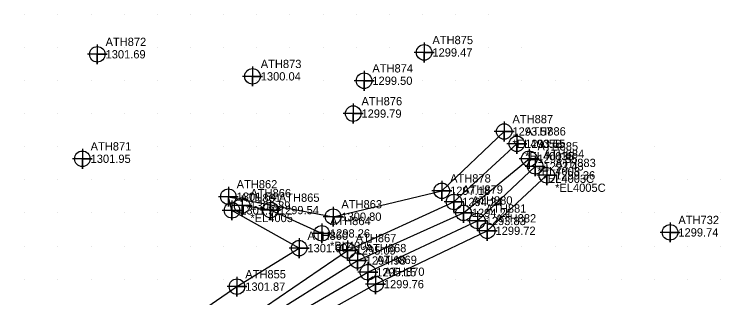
# Model space of a CAD drawing. Extents: x 1234484 to 1235382, y 695050 to 695510.
# Drawn here: x 1234936.8 to 1235150, y 695354.3 to 695440 of the extents above; entities that cross this region are included whole.
import ezdxf

# ---------------------------------------------------------------- set-up
doc = ezdxf.new("R2010")
doc.units = 0
for name, color, linetype in [('Exist DTM Breakline', 7, 'Continuous'), ('Exist DTM Breakline Cogo Comment', 7, 'Continuous'), ('Exist DTM Breakline Cogo Elevation', 7, 'Continuous'), ('Exist DTM Breakline Cogo Number', 7, 'Continuous'), ('Exist DTM Breakline Cogo Point CELL', 7, 'Continuous'), ('Exist DTM Breakline Underwater', 7, 'Continuous'), ('Exist DTM Drainline Cogo Comment', 7, 'Continuous'), ('Exist DTM Drainline Cogo Elevation', 7, 'Continuous'), ('Exist DTM Drainline Cogo Number', 7, 'Continuous'), ('Exist DTM Drainline Cogo Point CELL', 7, 'Continuous'), ('Exist DTM QL2 LIDAR Elevation Point', 7, 'Continuous'), ('Exist DTM Regular Point CELL', 7, 'Continuous'), ('Exist DTM Regular Point Cogo Elevation', 7, 'Continuous'), ('Exist DTM Regular Point Cogo Number', 7, 'Continuous'), ('Exist DTM Regular Point Underwater CELL', 7, 'Continuous'), ('Exist DTM Regular Point Underwater Cogo Comment', 7, 'Continuous'), ('Exist DTM Regular Point Underwater Cogo Elevation', 7, 'Continuous'), ('Exist DTM Regular Point Underwater Cogo Number', 7, 'Continuous'), ('Exist Hydro Stream or Body of Water', 7, 'Continuous')]:
    doc.layers.add(name, color=color, linetype=linetype)

msp = doc.modelspace()

# ---------------------------------------------------------------- linework, layer by layer
at = {"layer": 'Exist DTM Breakline'}
for points in [[(1234947.461, 695330.8), (1234981.356, 695342.155), (1235004.028, 695357.73), (1235022.786, 695369.361), (1235002.521, 695380.756), (1235001.421, 695384.893), (1235033.023, 695378.856), (1235065.819, 695386.67), (1235084.63, 695404.567)], [(1234978.66, 695327.276), (1234992.748, 695333.364), (1235012.047, 695339.528), (1235045.835, 695358.491), (1235079.523, 695374.606), (1235097.5, 695391.337)], [(1235029.585, 695373.809), (1235014.159, 695380.841), (1235005.572, 695382.217)]]:
    msp.add_lwpolyline(points, dxfattribs=at)
at = {"layer": 'Exist DTM Breakline Cogo Point CELL'}
for points in [[(1235084.63, 695407.567), (1235084.63, 695401.567), (1235084.63, 695404.567), (1235087.63, 695404.567), (1235081.63, 695404.567)], [(1235097.5, 695394.337), (1235097.5, 695388.337), (1235097.5, 695391.337), (1235100.5, 695391.337), (1235094.5, 695391.337)], [(1235065.819, 695389.67), (1235065.819, 695383.67), (1235065.819, 695386.67), (1235068.819, 695386.67), (1235062.819, 695386.67)], [(1235001.421, 695387.893), (1235001.421, 695381.893), (1235001.421, 695384.893), (1235004.421, 695384.893), (1234998.421, 695384.893)], [(1235005.572, 695385.217), (1235005.572, 695379.217), (1235005.572, 695382.217), (1235008.572, 695382.217), (1235002.572, 695382.217)], [(1235002.521, 695383.756), (1235002.521, 695377.756), (1235002.521, 695380.756), (1235005.521, 695380.756), (1234999.521, 695380.756)], [(1235014.159, 695383.841), (1235014.159, 695377.841), (1235014.159, 695380.841), (1235017.159, 695380.841), (1235011.159, 695380.841)], [(1235033.023, 695381.856), (1235033.023, 695375.856), (1235033.023, 695378.856), (1235036.023, 695378.856), (1235030.023, 695378.856)], [(1235079.523, 695377.606), (1235079.523, 695371.606), (1235079.523, 695374.606), (1235082.523, 695374.606), (1235076.523, 695374.606)], [(1235029.585, 695376.809), (1235029.585, 695370.809), (1235029.585, 695373.809), (1235032.585, 695373.809), (1235026.585, 695373.809)], [(1235022.786, 695372.361), (1235022.786, 695366.361), (1235022.786, 695369.361), (1235025.786, 695369.361), (1235019.786, 695369.361)], [(1235004.028, 695360.73), (1235004.028, 695354.73), (1235004.028, 695357.73), (1235007.028, 695357.73), (1235001.028, 695357.73)], [(1235045.835, 695361.491), (1235045.835, 695355.491), (1235045.835, 695358.491), (1235048.835, 695358.491), (1235042.835, 695358.491)]]:
    msp.add_lwpolyline(points, dxfattribs=at)
for centre in [(1235084.63, 695404.567), (1235097.5, 695391.337), (1235065.819, 695386.67), (1235001.421, 695384.893), (1235005.572, 695382.217), (1235002.521, 695380.756), (1235014.159, 695380.841), (1235033.023, 695378.856), (1235029.585, 695373.809), (1235079.523, 695374.606), (1235022.786, 695369.361), (1235045.835, 695358.491), (1235004.028, 695357.73)]:
    msp.add_circle(centre, 2.344, dxfattribs=at)
at = {"layer": 'Exist DTM Breakline Underwater'}
msp.add_lwpolyline([(1234766.421, 695209.389), (1234812.885, 695247.237), (1234843.411, 695272.621), (1234869.986, 695279.055), (1234895.378, 695289.036), (1234916.238, 695295.408), (1234934.131, 695306.081), (1234961.466, 695329.617), (1234991.436, 695342.664), (1235009.265, 695346.147), (1235040.352, 695365.623), (1235072.367, 695380.008), (1235092.174, 695396.335)], dxfattribs=at)
at = {"layer": 'Exist DTM Drainline Cogo Point CELL'}
for points in [[(1235088.448, 695403.861), (1235088.448, 695397.861), (1235088.448, 695400.861), (1235091.448, 695400.861), (1235085.448, 695400.861)], [(1235094.01, 695397.044), (1235094.01, 695391.044), (1235094.01, 695394.044), (1235097.01, 695394.044), (1235091.01, 695394.044)], [(1235069.491, 695386.302), (1235069.491, 695380.302), (1235069.491, 695383.302), (1235072.491, 695383.302), (1235066.491, 695383.302)], [(1235076.562, 695380.561), (1235076.562, 695374.561), (1235076.562, 695377.561), (1235079.562, 695377.561), (1235073.562, 695377.561)], [(1235037.336, 695371.653), (1235037.336, 695365.653), (1235037.336, 695368.653), (1235040.336, 695368.653), (1235034.336, 695368.653)], [(1235043.523, 695365.073), (1235043.523, 695359.073), (1235043.523, 695362.073), (1235046.523, 695362.073), (1235040.523, 695362.073)]]:
    msp.add_lwpolyline(points, dxfattribs=at)
for centre in [(1235088.448, 695400.861), (1235094.01, 695394.044), (1235069.491, 695383.302), (1235076.562, 695377.561), (1235037.336, 695368.653), (1235043.523, 695362.073)]:
    msp.add_circle(centre, 2.344, dxfattribs=at)
at = {"layer": 'Exist DTM QL2 LIDAR Elevation Point'}
for p, q in [((1234940, 695440), (1234940, 695440)), ((1234950, 695440), (1234950, 695440)), ((1234960, 695440), (1234960, 695440)), ((1234970, 695440), (1234970, 695440)), ((1234980, 695440), (1234980, 695440)), ((1234990, 695440), (1234990, 695440)), ((1235000, 695440), (1235000, 695440)), ((1235010, 695440), (1235010, 695440)), ((1235020, 695440), (1235020, 695440)), ((1235030, 695440), (1235030, 695440)), ((1235040, 695440), (1235040, 695440)), ((1235050, 695440), (1235050, 695440)), ((1235060, 695440), (1235060, 695440)), ((1235070, 695440), (1235070, 695440)), ((1235080, 695440), (1235080, 695440)), ((1234940, 695430), (1234940, 695430)), ((1234950, 695430), (1234950, 695430)), ((1234960, 695430), (1234960, 695430)), ((1234970, 695430), (1234970, 695430)), ((1234980, 695430), (1234980, 695430)), ((1234990, 695430), (1234990, 695430)), ((1235000, 695430), (1235000, 695430)), ((1235010, 695430), (1235010, 695430)), ((1235020, 695430), (1235020, 695430)), ((1235030, 695430), (1235030, 695430)), ((1235040, 695430), (1235040, 695430)), ((1235050, 695430), (1235050, 695430)), ((1235060, 695430), (1235060, 695430)), ((1235070, 695430), (1235070, 695430)), ((1235080, 695430), (1235080, 695430)), ((1235090, 695430), (1235090, 695430)), ((1234940, 695420), (1234940, 695420)), ((1234950, 695420), (1234950, 695420)), ((1234960, 695420), (1234960, 695420)), ((1234970, 695420), (1234970, 695420)), ((1234980, 695420), (1234980, 695420)), ((1234990, 695420), (1234990, 695420)), ((1235000, 695420), (1235000, 695420)), ((1235010, 695420), (1235010, 695420)), ((1235020, 695420), (1235020, 695420)), ((1235030, 695420), (1235030, 695420)), ((1235040, 695420), (1235040, 695420)), ((1235050, 695420), (1235050, 695420)), ((1235060, 695420), (1235060, 695420)), ((1235070, 695420), (1235070, 695420)), ((1235080, 695420), (1235080, 695420)), ((1235090, 695420), (1235090, 695420)), ((1235100, 695420), (1235100, 695420)), ((1235110, 695420), (1235110, 695420)), ((1234940, 695410), (1234940, 695410)), ((1234950, 695410), (1234950, 695410)), ((1234960, 695410), (1234960, 695410)), ((1234970, 695410), (1234970, 695410)), ((1234980, 695410), (1234980, 695410)), ((1234990, 695410), (1234990, 695410)), ((1235000, 695410), (1235000, 695410)), ((1235010, 695410), (1235010, 695410)), ((1235020, 695410), (1235020, 695410)), ((1235030, 695410), (1235030, 695410)), ((1235040, 695410), (1235040, 695410)), ((1235050, 695410), (1235050, 695410)), ((1235060, 695410), (1235060, 695410)), ((1235070, 695410), (1235070, 695410)), ((1235080, 695410), (1235080, 695410)), ((1234940, 695400), (1234940, 695400)), ((1234950, 695400), (1234950, 695400)), ((1234960, 695400), (1234960, 695400)), ((1234970, 695400), (1234970, 695400)), ((1234980, 695400), (1234980, 695400)), ((1234990, 695400), (1234990, 695400)), ((1235000, 695400), (1235000, 695400)), ((1235010, 695400), (1235010, 695400)), ((1235020, 695400), (1235020, 695400)), ((1235030, 695400), (1235030, 695400)), ((1235040, 695400), (1235040, 695400)), ((1235050, 695400), (1235050, 695400)), ((1235060, 695400), (1235060, 695400)), ((1235070, 695400), (1235070, 695400)), ((1235130, 695400), (1235130, 695400)), ((1234940, 695390), (1234940, 695390)), ((1234950, 695390), (1234950, 695390)), ((1234960, 695390), (1234960, 695390)), ((1234970, 695390), (1234970, 695390)), ((1234980, 695390), (1234980, 695390)), ((1234990, 695390), (1234990, 695390)), ((1235000, 695390), (1235000, 695390)), ((1235030, 695390), (1235030, 695390)), ((1235040, 695390), (1235040, 695390)), ((1235050, 695390), (1235050, 695390)), ((1235120, 695390), (1235120, 695390)), ((1235130, 695390), (1235130, 695390)), ((1235140, 695390), (1235140, 695390)), ((1235150, 695390), (1235150, 695390)), ((1234940, 695380), (1234940, 695380)), ((1234950, 695380), (1234950, 695380)), ((1234960, 695380), (1234960, 695380)), ((1234970, 695380), (1234970, 695380)), ((1234980, 695380), (1234980, 695380)), ((1234990, 695380), (1234990, 695380)), ((1235110, 695380), (1235110, 695380)), ((1235120, 695380), (1235120, 695380)), ((1235130, 695380), (1235130, 695380)), ((1235140, 695380), (1235140, 695380)), ((1235150, 695380), (1235150, 695380)), ((1234940, 695370), (1234940, 695370)), ((1234950, 695370), (1234950, 695370)), ((1234960, 695370), (1234960, 695370)), ((1234970, 695370), (1234970, 695370)), ((1234980, 695370), (1234980, 695370)), ((1234990, 695370), (1234990, 695370)), ((1235000, 695370), (1235000, 695370)), ((1235010, 695370), (1235010, 695370)), ((1235090, 695370), (1235090, 695370)), ((1235100, 695370), (1235100, 695370)), ((1235110, 695370), (1235110, 695370)), ((1235120, 695370), (1235120, 695370)), ((1235130, 695370), (1235130, 695370)), ((1235140, 695370), (1235140, 695370)), ((1235150, 695370), (1235150, 695370)), ((1234940, 695360), (1234940, 695360)), ((1234950, 695360), (1234950, 695360)), ((1234960, 695360), (1234960, 695360)), ((1234970, 695360), (1234970, 695360)), ((1234980, 695360), (1234980, 695360)), ((1234990, 695360), (1234990, 695360)), ((1235000, 695360), (1235000, 695360)), ((1235060, 695360), (1235060, 695360)), ((1235070, 695360), (1235070, 695360)), ((1235080, 695360), (1235080, 695360)), ((1235090, 695360), (1235090, 695360)), ((1235100, 695360), (1235100, 695360)), ((1235110, 695360), (1235110, 695360)), ((1235120, 695360), (1235120, 695360)), ((1235130, 695360), (1235130, 695360)), ((1235140, 695360), (1235140, 695360)), ((1235150, 695360), (1235150, 695360))]:
    msp.add_line(p, q, dxfattribs=at)
at = {"layer": 'Exist DTM Regular Point CELL'}
for points in [[(1234961.883, 695430.879), (1234961.883, 695424.879), (1234961.883, 695427.879), (1234964.883, 695427.879), (1234958.883, 695427.879)], [(1235060.481, 695431.438), (1235060.481, 695425.438), (1235060.481, 695428.438), (1235063.481, 695428.438), (1235057.481, 695428.438)], [(1235008.7, 695424.215), (1235008.7, 695418.215), (1235008.7, 695421.215), (1235011.7, 695421.215), (1235005.7, 695421.215)], [(1235042.367, 695422.889), (1235042.367, 695416.889), (1235042.367, 695419.889), (1235045.367, 695419.889), (1235039.367, 695419.889)], [(1235039.088, 695412.974), (1235039.088, 695406.974), (1235039.088, 695409.974), (1235042.088, 695409.974), (1235036.088, 695409.974)], [(1234957.375, 695399.332), (1234957.375, 695393.332), (1234957.375, 695396.332), (1234960.375, 695396.332), (1234954.375, 695396.332)], [(1235134.683, 695377.109), (1235134.683, 695371.109), (1235134.683, 695374.109), (1235137.683, 695374.109), (1235131.683, 695374.109)]]:
    msp.add_lwpolyline(points, dxfattribs=at)
for centre in [(1235060.481, 695428.438), (1234961.883, 695427.879), (1235008.7, 695421.215), (1235042.367, 695419.889), (1235039.088, 695409.974), (1234957.375, 695396.332), (1235134.683, 695374.109)]:
    msp.add_circle(centre, 2.344, dxfattribs=at)
at = {"layer": 'Exist DTM Regular Point Underwater CELL'}
for points in [[(1235092.174, 695399.335), (1235092.174, 695393.335), (1235092.174, 695396.335), (1235095.174, 695396.335), (1235089.174, 695396.335)], [(1235072.367, 695383.008), (1235072.367, 695377.008), (1235072.367, 695380.008), (1235075.367, 695380.008), (1235069.367, 695380.008)], [(1235040.352, 695368.623), (1235040.352, 695362.623), (1235040.352, 695365.623), (1235043.352, 695365.623), (1235037.352, 695365.623)]]:
    msp.add_lwpolyline(points, dxfattribs=at)
for centre in [(1235092.174, 695396.335), (1235072.367, 695380.008), (1235040.352, 695365.623)]:
    msp.add_circle(centre, 2.344, dxfattribs=at)
at = {"layer": 'Exist Hydro Stream or Body of Water'}
for points in [[(1234766.439, 695214.543), (1234809.451, 695250.146), (1234840.783, 695273.683), (1234870.231, 695281.467), (1234894.384, 695292.767), (1234915.014, 695298.345), (1234929.933, 695306.511), (1234953.845, 695329.807), (1234986.204, 695341.472), (1235008.526, 695348.915), (1235037.336, 695368.653), (1235069.491, 695383.302), (1235088.448, 695400.861)], [(1234938.044, 695305.366), (1234971.304, 695328.94), (1234992.169, 695338.626), (1235010.649, 695342.979), (1235043.523, 695362.073), (1235076.562, 695377.561), (1235094.01, 695394.044)]]:
    msp.add_lwpolyline(points, dxfattribs=at)

# ---------------------------------------------------------------- texts
at = {"layer": 'Exist DTM Breakline Cogo Comment'}
for s, p in [('*EL4005B', (1235087.13, 695399.567)), ('*EL4005C', (1235100, 695386.337)), ('*EL4005', (1235008.072, 695377.217)), ('*BL4005', (1235032.085, 695368.809))]:
    msp.add_text(s, height=2.5, dxfattribs=at).set_placement(p)
at = {"layer": 'Exist DTM Breakline Cogo Elevation'}
for s, p in [('1293.57', (1235087.13, 695403.317)), ('1299.36', (1235100, 695390.087)), ('1301.64', (1235003.921, 695383.643)), ('1297.18', (1235068.319, 695385.42)), ('1301.91', (1235005.021, 695379.506)), ('1300.89', (1235008.072, 695380.967)), ('1299.54', (1235016.659, 695379.591)), ('1300.80', (1235035.523, 695377.606)), ('1299.72', (1235082.023, 695373.356)), ('1298.26', (1235032.085, 695372.559)), ('1301.60', (1235025.286, 695368.111)), ('1301.87', (1235006.528, 695356.48)), ('1299.76', (1235048.335, 695357.241))]:
    msp.add_text(s, height=2.5, dxfattribs=at).set_placement(p)
at = {"layer": 'Exist DTM Breakline Cogo Number'}
for s, p in [('ATH887', (1235087.13, 695407.067)), ('ATH883', (1235100, 695393.837)), ('ATH878', (1235068.319, 695389.17)), ('ATH862', (1235003.921, 695387.393)), ('ATH866', (1235008.072, 695384.717)), ('ATH861', (1235005.021, 695383.256)), ('ATH865', (1235016.659, 695383.341)), ('ATH863', (1235035.523, 695381.356)), ('ATH882', (1235082.023, 695377.106)), ('ATH864', (1235032.085, 695376.309)), ('ATH860', (1235025.286, 695371.861)), ('ATH855', (1235006.528, 695360.23)), ('ATH870', (1235048.335, 695360.991))]:
    msp.add_text(s, height=2.5, dxfattribs=at).set_placement(p)
at = {"layer": 'Exist DTM Drainline Cogo Comment'}
for s, p in [('*EL4003B', (1235090.948, 695395.861)), ('*EL4003C', (1235096.51, 695389.044))]:
    msp.add_text(s, height=2.5, dxfattribs=at).set_placement(p)
at = {"layer": 'Exist DTM Drainline Cogo Elevation'}
for s, p in [('1293.55', (1235090.948, 695399.611)), ('1293.43', (1235096.51, 695392.794)), ('1294.24', (1235071.991, 695382.052)), ('1293.83', (1235079.062, 695376.311)), ('1295.09', (1235039.836, 695367.403)), ('1295.15', (1235046.023, 695360.823))]:
    msp.add_text(s, height=2.5, dxfattribs=at).set_placement(p)
at = {"layer": 'Exist DTM Drainline Cogo Number'}
for s, p in [('ATH886', (1235090.948, 695403.361)), ('ATH884', (1235096.51, 695396.544)), ('ATH879', (1235071.991, 695385.802)), ('ATH881', (1235079.062, 695380.061)), ('ATH867', (1235039.836, 695371.153)), ('ATH869', (1235046.023, 695364.573))]:
    msp.add_text(s, height=2.5, dxfattribs=at).set_placement(p)
at = {"layer": 'Exist DTM Regular Point Cogo Elevation'}
for s, p in [('1301.69', (1234964.383, 695426.629)), ('1299.47', (1235062.981, 695427.188)), ('1300.04', (1235011.2, 695419.965)), ('1299.50', (1235044.867, 695418.639)), ('1299.79', (1235041.588, 695408.724)), ('1301.95', (1234959.875, 695395.082)), ('1299.74', (1235137.183, 695372.859))]:
    msp.add_text(s, height=2.5, dxfattribs=at).set_placement(p)
at = {"layer": 'Exist DTM Regular Point Cogo Number'}
for s, p in [('ATH872', (1234964.383, 695430.379)), ('ATH875', (1235062.981, 695430.938)), ('ATH873', (1235011.2, 695423.715)), ('ATH874', (1235044.867, 695422.389)), ('ATH876', (1235041.588, 695412.474)), ('ATH871', (1234959.875, 695398.832)), ('ATH732', (1235137.183, 695376.609))]:
    msp.add_text(s, height=2.5, dxfattribs=at).set_placement(p)
at = {"layer": 'Exist DTM Regular Point Underwater Cogo Comment'}
msp.add_text('*EL4008', height=2.5, dxfattribs=at).set_placement((1235094.674, 695391.335))
at = {"layer": 'Exist DTM Regular Point Underwater Cogo Elevation'}
for s, p in [('1293.55', (1235094.674, 695395.085)), ('1294.21', (1235074.867, 695378.758)), ('1294.98', (1235042.852, 695364.373))]:
    msp.add_text(s, height=2.5, dxfattribs=at).set_placement(p)
at = {"layer": 'Exist DTM Regular Point Underwater Cogo Number'}
for s, p in [('ATH885', (1235094.674, 695398.835)), ('ATH880', (1235074.867, 695382.508)), ('ATH868', (1235042.852, 695368.123))]:
    msp.add_text(s, height=2.5, dxfattribs=at).set_placement(p)

doc.saveas('drawing.dxf')
